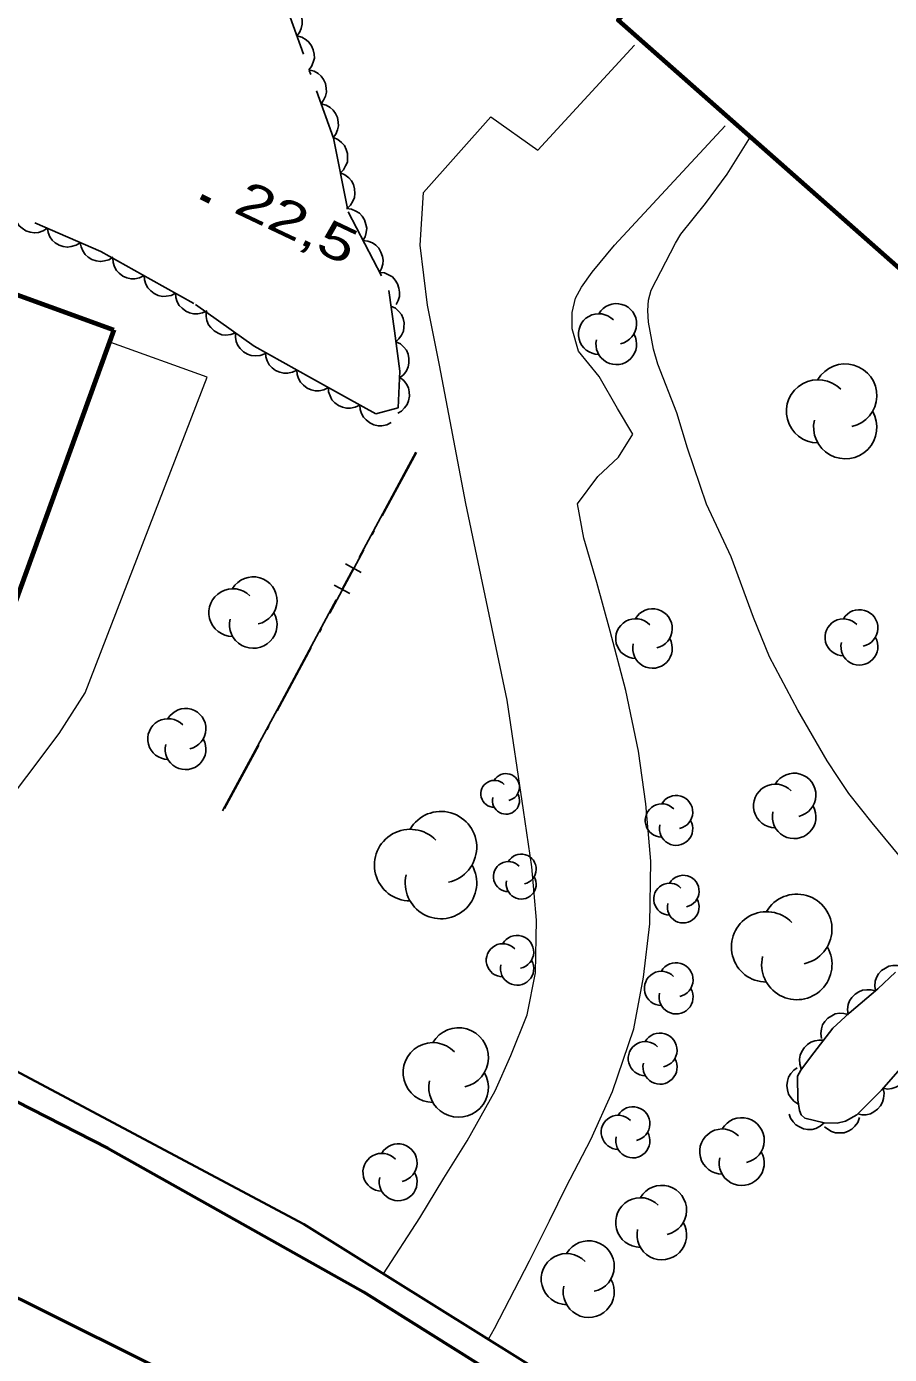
# Model space of a CAD drawing. Extents: x 356765 to 358572, y 5103174 to 5104650.
# Drawn here: x 357555.8 to 357591.8, y 5103718.2 to 5103773.6 of the extents above; entities that cross this region are included whole.
import ezdxf

# ---------------------------------------------------------------- set-up
doc = ezdxf.new("R2010")
doc.units = 0
doc.header["$LTSCALE"] = 0.6
doc.linetypes.add('DOT_DASHED', pattern=[7.7, 5, -1.2, 0.3, -1.2])
for name, color, linetype, lineweight in [('19', 7, 'Continuous', 13), ('2', 7, 'Continuous', 13), ('21', 7, 'Continuous', 53), ('22', 7, 'Continuous', 35), ('3', 7, 'Continuous', 140), ('31', 7, 'Continuous', 70), ('37', 7, 'Continuous', 13), ('44', 7, 'Continuous', 25)]:
    doc.layers.add(name, color=color, linetype=linetype, lineweight=lineweight)

msp = doc.modelspace()

# ---------------------------------------------------------------- linework, layer by layer
at = {"layer": '19'}
for points in [[(357570.67, 5103721.59), (357572.18, 5103723.92), (357573.19, 5103725.58), (357574.16, 5103727.13), (357575.32, 5103729.22), (357575.98, 5103730.68), (357576.66, 5103732.38), (357577, 5103734.13), (357577.05, 5103736.33), (357576.85, 5103738.55), (357576.5, 5103740.91), (357575.83, 5103745.5), (357574.1, 5103753.7), (357573, 5103759.46), (357572.5, 5103761.97), (357572.2, 5103764.47), (357572.34, 5103766.66), (357575.15, 5103769.81), (357577.11, 5103768.43), (357581.13, 5103772.81)], [(357575.05, 5103718.86), (357575.29, 5103719.3), (357576.75, 5103722.13), (357577.59, 5103723.79), (357578.29, 5103725.21), (357579.31, 5103727.19), (357580.21, 5103729.18), (357581.1, 5103731.8), (357581.51, 5103733.95), (357581.77, 5103736.18), (357581.82, 5103738.79), (357581.6, 5103741.18), (357581.3, 5103743.37), (357580.77, 5103745.9), (357580.12, 5103748.37), (357579.56, 5103750.4), (357579.02, 5103752.25), (357578.76, 5103753.69), (357579.6, 5103754.83), (357580.46, 5103755.63), (357581.06, 5103756.59), (357580.42, 5103757.66), (357579.66, 5103758.99), (357578.8, 5103760.05), (357578.54, 5103760.98), (357578.53, 5103761.66), (357578.67, 5103762.26), (357578.92, 5103762.71), (357579.37, 5103763.34), (357580.3, 5103764.47), (357584.92, 5103769.44)], [(357548.96, 5103733.25), (357557.14, 5103744.11), (357558.23, 5103745.8), (357563.32, 5103758.96), (357559.3, 5103760.41)]]:
    msp.add_lwpolyline(points, dxfattribs=at)
at = {"layer": '2'}
msp.add_lwpolyline([(357592.44, 5103738.7), (357591.04, 5103740.38), (357590.07, 5103741.61), (357589.62, 5103742.28), (357589.17, 5103742.97), (357587.95, 5103745.08), (357586.77, 5103747.3), (357586.1, 5103748.94), (357585.16, 5103751.47), (357584.14, 5103753.67), (357583.34, 5103756), (357582.9, 5103757.48), (357582.11, 5103759.51), (357581.93, 5103760.13), (357581.72, 5103761.26), (357581.69, 5103761.74), (357581.72, 5103762.17), (357581.83, 5103762.59), (357582.85, 5103764.55), (357583.06, 5103764.92), (357584.1, 5103766.2), (357585, 5103767.42), (357585.97, 5103768.98)], dxfattribs=at)
at = {"layer": '21'}
for points in [[(357338.61, 5103773.13), (357340.11, 5103772.62), (357343.3, 5103771.76), (357350.78, 5103769.83), (357368.94, 5103766.05), (357392.09, 5103762.41), (357416.79, 5103758.21), (357441.26, 5103754.15), (357468.58, 5103749.26), (357504.23, 5103742.99), (357523.34, 5103739.7), (357536.22, 5103737.01), (357542.95, 5103734.88), (357550.23, 5103731.38), (357559.17, 5103726.82), (357569.84, 5103720.84), (357583.91, 5103712.01), (357595.28, 5103704.43), (357600.89, 5103700.45), (357609.42, 5103694), (357620.2, 5103685.76)], [(357511.52, 5103734.46), (357526.07, 5103731.29), (357532.07, 5103730.08), (357536.9, 5103728.84), (357545.61, 5103725.43), (357556.4, 5103720.09), (357561.12, 5103717.74), (357566.51, 5103714.48), (357571.32, 5103711.63), (357575.88, 5103708.84), (357579.94, 5103706.29), (357584.25, 5103703.34), (357588.47, 5103700.62), (357593.04, 5103697.26), (357597.8, 5103693.8), (357604.89, 5103688.51)]]:
    msp.add_lwpolyline(points, dxfattribs=at)
at = {"layer": '22'}
msp.add_lwpolyline([(357468.95, 5103750.64), (357513.48, 5103742.84), (357531.11, 5103739.41), (357539.54, 5103737.41), (357545.5, 5103734.97), (357554.23, 5103730.63), (357567.35, 5103723.66), (357583.76, 5103713.42), (357597.55, 5103704.05), (357603.13, 5103700.17), (357610.19, 5103694.78), (357623.39, 5103684.71)], dxfattribs=at)
at = {"layer": '3'}
msp.add_line((357563.06, 5103766.49), (357563.42, 5103766.32), dxfattribs=at)
at = {"layer": '31'}
for points in [[(357587.88, 5103782.26), (357591.74, 5103778.84), (357592.94, 5103780.21), (357604.53, 5103769.98), (357598, 5103762.59), (357594.64, 5103765.55), (357592.54, 5103763.18), (357580.45, 5103773.84), (357587.88, 5103782.26)], [(357559.42, 5103760.94), (357555.02, 5103748.76), (357552.36, 5103749.72), (357551.71, 5103747.94), (357541.96, 5103751.46), (357545.5, 5103761.26), (357546.67, 5103760.83), (357547.45, 5103762.98), (357553.24, 5103760.88), (357553.98, 5103762.91), (357559.42, 5103760.94)]]:
    msp.add_lwpolyline(points, close=True, dxfattribs=at)
at = {"layer": '37', "linetype": 'DOT_DASHED', "lineweight": 25}
msp.add_line((357572.04, 5103755.83), (357563.98, 5103740.87), dxfattribs=at)
at = {"layer": '37', "lineweight": 25}
for p, q in [((357572.02, 5103755.84), (357569.65, 5103751.44)), ((357569.41, 5103751), (357568.94, 5103750.12)), ((357569.74, 5103750.82), (357569.08, 5103751.18)), ((357569.27, 5103749.94), (357568.61, 5103750.3)), ((357568.7, 5103749.68), (357566.33, 5103745.28)), ((357566.33, 5103745.28), (357563.96, 5103740.88))]:
    msp.add_line(p, q, dxfattribs=at)
at = {"layer": '44', "linetype": 'DOT_DASHED'}
for points in [[(357564.77, 5103779.61), (357568.58, 5103768.93), (357569.2, 5103765.85), (357570.89, 5103762.58), (357571.12, 5103760.89), (357571.35, 5103759.21), (357571.28, 5103757.69), (357570.35, 5103757.43), (357569.16, 5103758.09), (357567.67, 5103758.92), (357566.47, 5103759.59), (357565.28, 5103760.25), (357562.76, 5103762.04), (357560.97, 5103763.04), (357558.88, 5103764.2), (357555.66, 5103765.6)], [(357592.33, 5103730.25), (357591.43, 5103729.24), (357590.4, 5103728.21), (357589.93, 5103727.95), (357589.58, 5103727.86), (357589.04, 5103727.88), (357588.23, 5103728.08), (357588.09, 5103728.21), (357588.02, 5103728.4), (357587.95, 5103728.84), (357587.93, 5103729.83), (357588.07, 5103730.07), (357588.47, 5103730.62), (357589.41, 5103731.83), (357590.09, 5103732.45), (357591.28, 5103733.47), (357592.02, 5103734.16)]]:
    msp.add_lwpolyline(points, dxfattribs=at)
at = {"layer": '44'}
for points in [[(357566.56, 5103774.6), (357566.76, 5103774.55), (357566.93, 5103774.44), (357567.06, 5103774.34), (357567.16, 5103774.2), (357567.24, 5103774.03), (357567.27, 5103773.84), (357567.28, 5103773.68), (357567.24, 5103773.5), (357567.17, 5103773.33), (357567.06, 5103773.19)], [(357567.06, 5103773.19), (357567.26, 5103773.14), (357567.44, 5103773.03), (357567.56, 5103772.93), (357567.66, 5103772.78), (357567.74, 5103772.61), (357567.77, 5103772.43), (357567.79, 5103772.26), (357567.74, 5103772.09), (357567.67, 5103771.92), (357567.56, 5103771.78)], [(357567.56, 5103771.78), (357567.77, 5103771.72), (357567.94, 5103771.62), (357568.07, 5103771.51), (357568.17, 5103771.37), (357568.25, 5103771.2), (357568.28, 5103771.01), (357568.29, 5103770.85), (357568.25, 5103770.68), (357568.17, 5103770.51), (357568.07, 5103770.36)], [(357568.07, 5103770.36), (357568.27, 5103770.31), (357568.44, 5103770.21), (357568.57, 5103770.1), (357568.67, 5103769.96), (357568.75, 5103769.79), (357568.78, 5103769.6), (357568.79, 5103769.44), (357568.75, 5103769.27), (357568.68, 5103769.1), (357568.57, 5103768.95)], [(357568.58, 5103768.95), (357568.77, 5103768.87), (357568.92, 5103768.74), (357569.04, 5103768.62), (357569.11, 5103768.46), (357569.17, 5103768.29), (357569.17, 5103768.09), (357569.16, 5103767.93), (357569.09, 5103767.77), (357569, 5103767.61), (357568.87, 5103767.48)], [(357568.87, 5103767.48), (357569.06, 5103767.4), (357569.22, 5103767.27), (357569.33, 5103767.15), (357569.41, 5103766.99), (357569.46, 5103766.81), (357569.47, 5103766.62), (357569.46, 5103766.46), (357569.39, 5103766.3), (357569.29, 5103766.14), (357569.17, 5103766.01)], [(357569.12, 5103766), (357569.33, 5103765.97), (357569.52, 5103765.89), (357569.66, 5103765.8), (357569.78, 5103765.67), (357569.88, 5103765.52), (357569.93, 5103765.33), (357569.97, 5103765.18), (357569.95, 5103765), (357569.9, 5103764.82), (357569.81, 5103764.66)], [(357556.65, 5103765.17), (357556.47, 5103765.06), (357556.28, 5103765), (357556.11, 5103764.98), (357555.94, 5103765.01), (357555.76, 5103765.07), (357555.6, 5103765.17), (357555.48, 5103765.27), (357555.38, 5103765.42), (357555.31, 5103765.59), (357555.27, 5103765.77)], [(357558.02, 5103764.57), (357557.85, 5103764.46), (357557.65, 5103764.41), (357557.49, 5103764.38), (357557.31, 5103764.41), (357557.14, 5103764.47), (357556.98, 5103764.57), (357556.85, 5103764.68), (357556.76, 5103764.82), (357556.68, 5103764.99), (357556.65, 5103765.17)], [(357559.4, 5103763.97), (357559.22, 5103763.86), (357559.03, 5103763.81), (357558.86, 5103763.78), (357558.69, 5103763.81), (357558.51, 5103763.87), (357558.35, 5103763.97), (357558.23, 5103764.08), (357558.13, 5103764.23), (357558.06, 5103764.4), (357558.02, 5103764.57)], [(357569.81, 5103764.66), (357570.02, 5103764.64), (357570.21, 5103764.56), (357570.35, 5103764.47), (357570.47, 5103764.34), (357570.56, 5103764.18), (357570.62, 5103764), (357570.66, 5103763.84), (357570.64, 5103763.67), (357570.59, 5103763.49), (357570.5, 5103763.33)], [(357560.69, 5103763.2), (357560.5, 5103763.1), (357560.3, 5103763.07), (357560.14, 5103763.06), (357559.97, 5103763.1), (357559.8, 5103763.18), (357559.65, 5103763.3), (357559.53, 5103763.41), (357559.45, 5103763.57), (357559.39, 5103763.75), (357559.38, 5103763.92)], [(357562, 5103762.47), (357561.81, 5103762.37), (357561.61, 5103762.34), (357561.45, 5103762.33), (357561.27, 5103762.37), (357561.11, 5103762.45), (357560.96, 5103762.57), (357560.84, 5103762.69), (357560.76, 5103762.84), (357560.7, 5103763.02), (357560.69, 5103763.2)], [(357570.5, 5103763.33), (357570.71, 5103763.31), (357570.9, 5103763.22), (357571.04, 5103763.14), (357571.15, 5103763.01), (357571.25, 5103762.85), (357571.31, 5103762.67), (357571.34, 5103762.51), (357571.33, 5103762.33), (357571.28, 5103762.16), (357571.19, 5103762)], [(357563.31, 5103761.73), (357563.12, 5103761.64), (357562.92, 5103761.61), (357562.75, 5103761.6), (357562.58, 5103761.64), (357562.42, 5103761.72), (357562.27, 5103761.84), (357562.15, 5103761.95), (357562.07, 5103762.11), (357562.01, 5103762.29), (357562, 5103762.47)], [(357564.49, 5103760.81), (357564.3, 5103760.74), (357564.09, 5103760.72), (357563.93, 5103760.73), (357563.77, 5103760.8), (357563.61, 5103760.89), (357563.47, 5103761.03), (357563.37, 5103761.15), (357563.3, 5103761.32), (357563.27, 5103761.5), (357563.27, 5103761.68)], [(357570.98, 5103761.93), (357571.17, 5103761.84), (357571.31, 5103761.7), (357571.42, 5103761.57), (357571.49, 5103761.41), (357571.53, 5103761.23), (357571.52, 5103761.04), (357571.5, 5103760.88), (357571.42, 5103760.72), (357571.31, 5103760.56), (357571.18, 5103760.44)], [(357565.72, 5103759.94), (357565.52, 5103759.87), (357565.32, 5103759.85), (357565.15, 5103759.87), (357564.99, 5103759.93), (357564.83, 5103760.02), (357564.69, 5103760.16), (357564.59, 5103760.28), (357564.53, 5103760.45), (357564.49, 5103760.63), (357564.49, 5103760.81)], [(357571.18, 5103760.44), (357571.37, 5103760.35), (357571.52, 5103760.21), (357571.62, 5103760.09), (357571.69, 5103759.92), (357571.73, 5103759.74), (357571.72, 5103759.55), (357571.7, 5103759.39), (357571.62, 5103759.23), (357571.52, 5103759.08), (357571.38, 5103758.96)], [(357567.06, 5103759.26), (357566.87, 5103759.17), (357566.67, 5103759.13), (357566.51, 5103759.13), (357566.34, 5103759.17), (357566.17, 5103759.24), (357566.02, 5103759.36), (357565.9, 5103759.48), (357565.82, 5103759.64), (357565.76, 5103759.81), (357565.75, 5103759.99)], [(357568.37, 5103758.53), (357568.18, 5103758.44), (357567.98, 5103758.4), (357567.82, 5103758.4), (357567.65, 5103758.44), (357567.48, 5103758.51), (357567.33, 5103758.63), (357567.21, 5103758.75), (357567.13, 5103758.91), (357567.07, 5103759.08), (357567.06, 5103759.26)], [(357571.34, 5103758.96), (357571.51, 5103758.83), (357571.63, 5103758.67), (357571.71, 5103758.52), (357571.74, 5103758.35), (357571.75, 5103758.17), (357571.71, 5103757.98), (357571.66, 5103757.82), (357571.55, 5103757.68), (357571.42, 5103757.55), (357571.27, 5103757.46)], [(357569.68, 5103757.8), (357569.49, 5103757.71), (357569.29, 5103757.67), (357569.13, 5103757.67), (357568.96, 5103757.71), (357568.79, 5103757.78), (357568.64, 5103757.9), (357568.52, 5103758.02), (357568.44, 5103758.18), (357568.38, 5103758.35), (357568.37, 5103758.53)], [(357570.99, 5103757.07), (357570.81, 5103756.98), (357570.6, 5103756.94), (357570.44, 5103756.94), (357570.27, 5103756.98), (357570.1, 5103757.06), (357569.95, 5103757.18), (357569.84, 5103757.29), (357569.75, 5103757.45), (357569.7, 5103757.62), (357569.68, 5103757.8)], [(357591.18, 5103733.38), (357591.15, 5103733.58), (357591.17, 5103733.78), (357591.22, 5103733.94), (357591.31, 5103734.09), (357591.44, 5103734.23), (357591.6, 5103734.33), (357591.74, 5103734.41), (357591.91, 5103734.44), (357592.1, 5103734.44), (357592.28, 5103734.4)], [(357590.04, 5103732.4), (357590.01, 5103732.61), (357590.05, 5103732.81), (357590.1, 5103732.97), (357590.2, 5103733.11), (357590.33, 5103733.24), (357590.49, 5103733.34), (357590.64, 5103733.41), (357590.82, 5103733.43), (357591, 5103733.43), (357591.17, 5103733.38)], [(357588.93, 5103731.39), (357588.9, 5103731.6), (357588.93, 5103731.8), (357588.98, 5103731.96), (357589.07, 5103732.11), (357589.2, 5103732.24), (357589.36, 5103732.34), (357589.5, 5103732.42), (357589.68, 5103732.45), (357589.86, 5103732.44), (357590.04, 5103732.4)], [(357588.09, 5103730.13), (357588.03, 5103730.33), (357588.02, 5103730.53), (357588.04, 5103730.7), (357588.11, 5103730.86), (357588.21, 5103731.01), (357588.35, 5103731.14), (357588.48, 5103731.24), (357588.65, 5103731.3), (357588.83, 5103731.33), (357589.01, 5103731.32)], [(357587.95, 5103728.67), (357587.78, 5103728.78), (357587.65, 5103728.94), (357587.56, 5103729.08), (357587.51, 5103729.25), (357587.49, 5103729.43), (357587.52, 5103729.62), (357587.56, 5103729.78), (357587.65, 5103729.93), (357587.78, 5103730.07), (357587.92, 5103730.17)], [(357592.5, 5103730.44), (357592.55, 5103730.23), (357592.54, 5103730.03), (357592.51, 5103729.87), (357592.43, 5103729.71), (357592.32, 5103729.56), (357592.17, 5103729.44), (357592.03, 5103729.36), (357591.86, 5103729.31), (357591.68, 5103729.29), (357591.5, 5103729.32)], [(357591.5, 5103729.31), (357591.54, 5103729.11), (357591.52, 5103728.9), (357591.48, 5103728.74), (357591.39, 5103728.59), (357591.27, 5103728.45), (357591.12, 5103728.34), (357590.98, 5103728.26), (357590.8, 5103728.22), (357590.62, 5103728.22), (357590.44, 5103728.25)], [(357589.04, 5103727.88), (357588.88, 5103727.74), (357588.7, 5103727.65), (357588.54, 5103727.6), (357588.36, 5103727.6), (357588.18, 5103727.63), (357588.01, 5103727.71), (357587.86, 5103727.79), (357587.75, 5103727.92), (357587.64, 5103728.07), (357587.58, 5103728.24)], [(357590.51, 5103728.1), (357590.44, 5103727.9), (357590.32, 5103727.74), (357590.2, 5103727.62), (357590.05, 5103727.53), (357589.87, 5103727.47), (357589.68, 5103727.46), (357589.52, 5103727.46), (357589.35, 5103727.52), (357589.19, 5103727.61), (357589.05, 5103727.72)]]:
    msp.add_lwpolyline(points, dxfattribs=at)
for centre, radius, start, end in [((357580.3742, 5103761.1833), 0.8481, 282.26917, 149.72626), ((357579.6448, 5103760.7593), 0.8481, 44.11537, 269.80396), ((357580.3742, 5103760.3352), 0.8481, 166.93686, 29.62122), ((357589.9209, 5103758.1994), 1.3189, 282.26917, 149.72626), ((357588.7866, 5103757.54), 1.3189, 44.11537, 269.80396), ((357589.9209, 5103756.8805), 1.3189, 166.93686, 29.62122), ((357565.235, 5103749.6494), 0.9937, 282.26917, 149.72626), ((357564.3805, 5103749.1526), 0.9937, 44.11537, 269.80396), ((357581.8847, 5103748.4814), 0.8253, 282.26917, 149.72626), ((357590.5117, 5103748.5027), 0.7703, 282.26917, 149.72626), ((357565.235, 5103748.6557), 0.9937, 166.93686, 29.62122), ((357581.175, 5103748.0687), 0.8253, 44.11537, 269.80396), ((357589.8493, 5103748.1175), 0.7703, 44.11537, 269.80396), ((357581.8847, 5103747.6561), 0.8253, 166.93686, 29.62122), ((357590.5117, 5103747.7323), 0.7703, 166.93686, 29.62122), ((357562.4145, 5103744.3036), 0.8487, 282.26917, 149.72626), ((357561.6846, 5103743.8793), 0.8487, 44.11537, 269.80396), ((357562.4145, 5103743.4549), 0.8487, 166.93686, 29.62122), ((357575.2907, 5103741.5928), 0.5637, 44.11537, 269.80396), ((357575.7754, 5103741.8746), 0.5637, 282.26917, 149.72626), ((357587.79, 5103741.5455), 0.9097, 282.26917, 149.72626), ((357575.7754, 5103741.311), 0.5637, 166.93686, 29.62122), ((357582.8696, 5103740.8325), 0.6934, 282.26917, 149.72626), ((357587.0076, 5103741.0907), 0.9097, 44.11537, 269.80396), ((357582.2733, 5103740.4857), 0.6934, 44.11537, 269.80396), ((357587.79, 5103740.6358), 0.9097, 166.93686, 29.62122), ((357573.063, 5103739.3697), 1.4916, 282.26917, 149.72626), ((357582.8696, 5103740.139), 0.6934, 166.93686, 29.62122), ((357571.7802, 5103738.6239), 1.4916, 44.11537, 269.80396), ((357575.8736, 5103738.1442), 0.6249, 44.11537, 269.80396), ((357576.411, 5103738.4566), 0.6249, 282.26917, 149.72626), ((357573.063, 5103737.8781), 1.4916, 166.93686, 29.62122), ((357583.1667, 5103737.5362), 0.6624, 282.26917, 149.72626), ((357576.411, 5103737.8318), 0.6249, 166.93686, 29.62122), ((357582.597, 5103737.205), 0.6624, 44.11537, 269.80396), ((357583.1667, 5103736.8738), 0.6624, 166.93686, 29.62122), ((357587.9028, 5103735.947), 1.4673, 282.26917, 149.72626), ((357586.641, 5103735.2133), 1.4673, 44.11537, 269.80396), ((357576.2391, 5103735.0018), 0.6921, 282.26917, 149.72626), ((357575.6438, 5103734.6557), 0.6921, 44.11537, 269.80396), ((357587.9028, 5103734.4797), 1.4673, 166.93686, 29.62122), ((357576.2391, 5103734.3096), 0.6921, 166.93686, 29.62122), ((357582.8671, 5103733.8418), 0.7112, 282.26917, 149.72626), ((357582.2554, 5103733.4862), 0.7112, 44.11537, 269.80396), ((357582.8671, 5103733.1305), 0.7112, 166.93686, 29.62122), ((357573.7997, 5103730.6004), 1.2443, 282.26917, 149.72626), ((357582.197, 5103730.9117), 0.7112, 282.26917, 149.72626), ((357572.7296, 5103729.9783), 1.2443, 44.11537, 269.80396), ((357581.5854, 5103730.5562), 0.7112, 44.11537, 269.80396), ((357582.197, 5103730.2006), 0.7112, 166.93686, 29.62122), ((357573.7997, 5103729.3561), 1.2443, 166.93686, 29.62122), ((357581.067, 5103727.8417), 0.7111, 282.26917, 149.72626), ((357580.4554, 5103727.4861), 0.7111, 44.11537, 269.80396), ((357585.6034, 5103727.1523), 0.9418, 282.26917, 149.72626), ((357581.067, 5103727.1306), 0.7111, 166.93686, 29.62122), ((357584.7934, 5103726.6814), 0.9418, 44.11537, 269.80396), ((357570.6005, 5103725.8179), 0.7901, 44.11537, 269.80396), ((357571.28, 5103726.213), 0.7901, 282.26917, 149.72626), ((357585.6034, 5103726.2105), 0.9418, 166.93686, 29.62122), ((357571.28, 5103725.4229), 0.7901, 166.93686, 29.62122), ((357582.2719, 5103724.2406), 1.0341, 282.26917, 149.72626), ((357581.3826, 5103723.7235), 1.0341, 44.11537, 269.80396), ((357582.2719, 5103723.2064), 1.0341, 166.93686, 29.62122), ((357579.2249, 5103721.8968), 1.0652, 282.26917, 149.72626), ((357578.3088, 5103721.3642), 1.0652, 44.11537, 269.80396), ((357579.2249, 5103720.8316), 1.0652, 166.93686, 29.62122)]:
    msp.add_arc(centre, radius, start, end, dxfattribs=at)

# ---------------------------------------------------------------- texts
at = {"layer": '3', "width": 1.35}
msp.add_text('22,5   ', height=1.5, rotation=334.619, dxfattribs=at).set_placement((357564.36, 5103765.86))

doc.saveas('drawing.dxf')
